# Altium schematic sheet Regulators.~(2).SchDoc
size A4
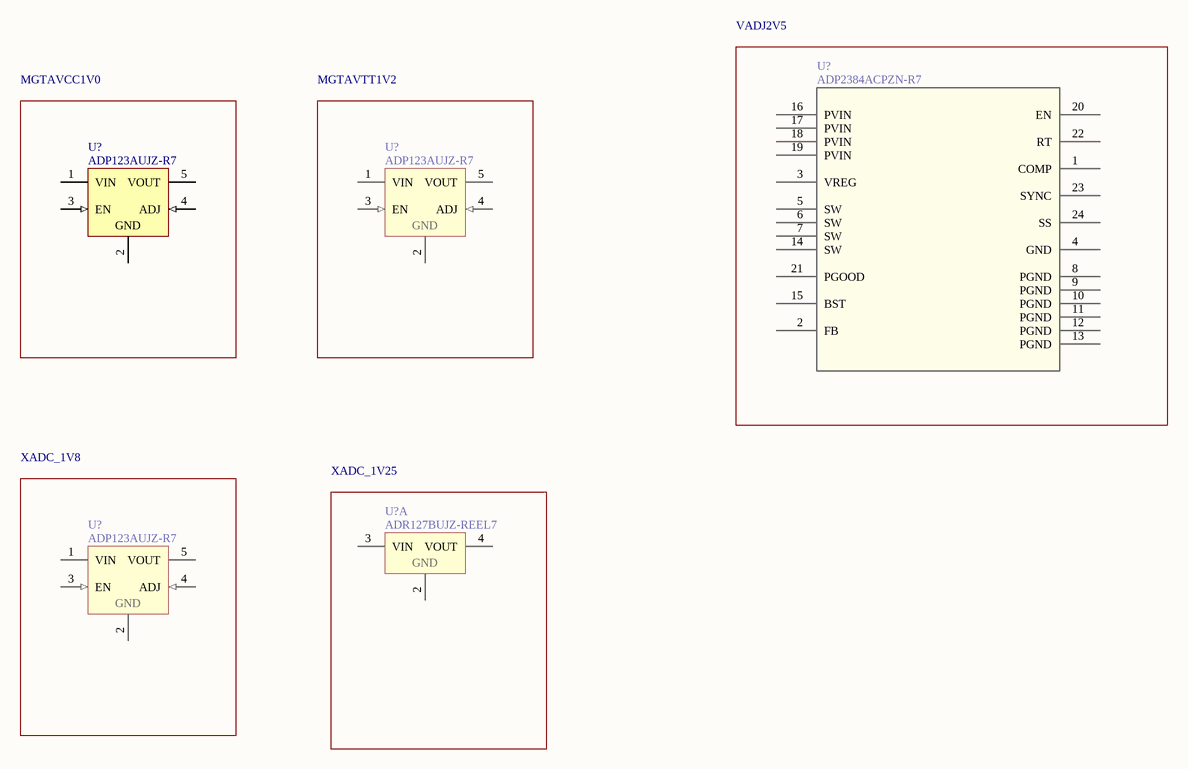
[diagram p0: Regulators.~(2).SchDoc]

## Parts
(Parts that share a designator on the sheet are numbered #1, #2 ... from top to bottom, then left to right.)
U?#1  ADP2384ACPZN-R7  [CP_24_12]
U?#2  ADP123AUJZ-R7  [ADI-UJ-5_N]
U?#3  ADP123AUJZ-R7  [ADI-UJ-5_N]
U?#4  ADR127BUJZ-REEL7  [ADI-UJ-6_N]  (part A of 2)
U?#5  ADP123AUJZ-R7  [ADI-UJ-5_N]

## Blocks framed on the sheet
VADJ2V5: U?#1
MGTAVCC1V0: U?#2
MGTAVTT1V2: U?#3
XADC_1V8: U?#5
XADC_1V25: U?#4

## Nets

Not connected (* = marked no-connect by the designer): U?#1 1(COMP) 2(FB) 3(VREG) 4(GND) 5(SW) 6(SW) 7(SW) 8(PGND) 9(PGND) 10(PGND) 11(PGND) 12(PGND) 13(PGND) 14(SW) 15(BST) 16(PVIN) 17(PVIN) 18(PVIN) 19(PVIN) 20(EN) 21(PGOOD) 22(RT) 23(SYNC) 24(SS); U?#2 1(VIN) 2(GND) 3(EN) 4(ADJ) 5(VOUT); U?#3 1(VIN) 2(GND) 3(EN) 4(ADJ) 5(VOUT); U?#4 2(GND) 3(VIN) 4(VOUT); U?#5 1(VIN) 2(GND) 3(EN) 4(ADJ) 5(VOUT)

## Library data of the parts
U?#1 = ADP2384ACPZN-R7: Imported
U?#2 U?#3 U?#5 = ADP123AUJZ-R7: 300 mA, Low Quiescent Current, CMOS Linear Regulator, 2.3 to 5.5 V Vin, 0.8 to 5 V Vout, Industrial, 5-pin SOT23 (UJ-5), Reel; Manufacturer: Analog Devices; Iout max: 300mA; Supply Current IGND @ Small Load: 45uA; Vin (max) (V): 5.5; Vin (min) (V): 2.3; Vout Adjustable Range: 0.8V to 5V
U?#4 = ADR127BUJZ-REEL7: Precision, Micropower LDO Voltage Reference in TSOT, 1.25 V Output, 2.7 to 18 V Supply, Industrial, 6-pin SOT23 (UJ-6), Reel; Manufacturer: Analog Devices; Max V Supply (V): 18; Min V Supply (V): 2.7; Ref Out TC (ppm/C): 3; Vout: 1.25V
